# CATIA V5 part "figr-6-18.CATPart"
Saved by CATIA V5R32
Part number: Part1
Bounding box of the stored display mesh (mm): x 0 to 150, y -70 to 70, z -150 to 69.804
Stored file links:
  D:\PROJECTS\Project 2022\CATIA V5 6R 2022\Resources\Part Files\c06_catia_v5_6r2022_prt\figr-6-18.CATPart
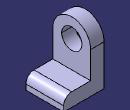
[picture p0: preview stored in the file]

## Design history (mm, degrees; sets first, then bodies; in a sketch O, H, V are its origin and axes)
Body1 (main body)
  Sketch1 on yz-plane, origin (0, 0, 0), H (0, 1, 0), V (0, 0, 1)
    arc A1 centre (0, 0) radius 70 from (70, 0) to (-70, 0) ccw
    point P1 (70, 0)
    point P2 (-70, 0)
    line L1 (-70, 0) -> (-70, -150)
    line L2 (-70, -150) -> (70, -150)
    line L3 (70, -150) -> (70, 0)
    circle A2 centre (0, 0) radius 37.5
    radius A1 = 70
    radius A2 = 37.5
    distance O L2 = 150
    coincidence: P1 H, P2 H
    tangency: L1 A1, L3 A1
    horizontal: L2 H
  Pad1: profile Sketch1, direction (1, 0, 0), length 50
  Sketch2 on face of Pad1, origin (50, 0, 0), H (0, 1, 0), V (0, 0, 1)
    line L1 (-70, -150) -> (70, -150)
    line L2 (70, -150) -> (70, -100)
    line L3 (70, -100) -> (-70, -100)
    line L4 (-70, -100) -> (-70, -150)
    reference projected line E1 (-70, -150) -> (70, -150) from edge [face of Pad1 | face of Pad1]
    reference projected line E2 (-70, 0) -> (-70, -150) from edge [face of Pad1 | face of Pad1]
    reference projected line E3 (70, -150) -> (70, 0) from edge [face of Pad1 | face of Pad1]
    length L2 = 50
    horizontal: L1 H, L3 H
    vertical: L2 V, L4 V
    coincidence: L1 E1, E2 L4, L2 E3
  Pad2: profile Sketch2, direction (1, 0, 0), length 100
  Fillet1: radius 30, on edge [face of Pad2 | face of Pad2]
  Sketch3 on face of Pad1, origin (50, 0, 0), H (0, 1, 0), V (0, 0, 1)
    point P1 (45.5554, 53.148)
    reference projected arc E1 centre (0, 0) radius 70 from (70, 0) to (-70, 0) ccw from edge [face of Pad1 | face of Pad1]
    coincidence: P1 E1
  Sketch4 on face of Pad2, origin (0, 0, -100), H (1, 0, 0), V (0, 1, 0)
    point P1 (110, 20)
